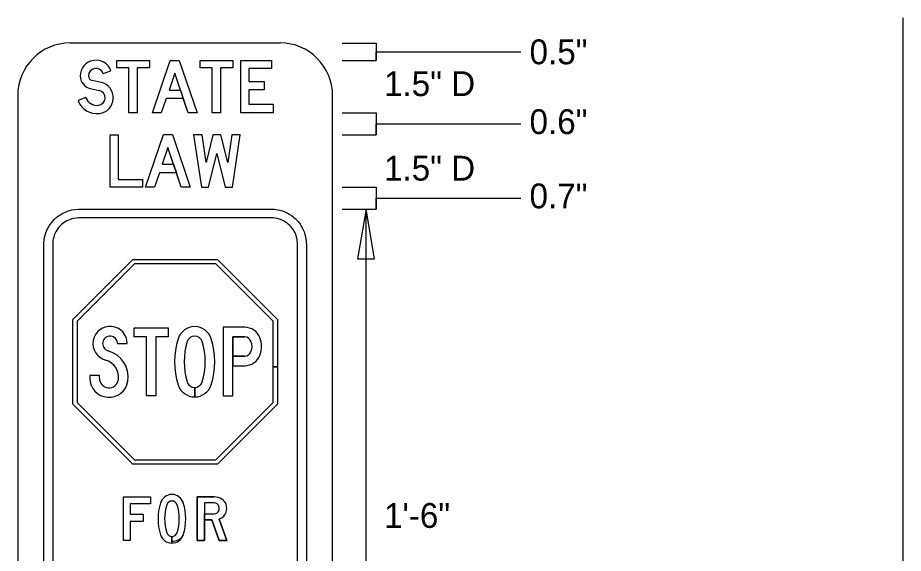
# Model space of a CAD drawing. Extents: x 0 to 770, y 0 to 495.
# Drawn here: x 260.2 to 385, y 419.5 to 495 of the extents above; entities that cross this region are included whole.
import ezdxf

# ---------------------------------------------------------------- set-up
doc = ezdxf.new("R2010")
doc.units = 0
for name, color, linetype in [('Default', 7, 'Continuous'), ('Dimension', 7, 'Continuous'), ('GSBWFill', 7, 'Continuous'), ('GSColorFill', 7, 'Continuous'), ('GSDims', 7, 'Continuous'), ('GSOutline', 7, 'Continuous'), ('SheetLines_dp', 7, 'Continuous'), ('TextStructures', 7, 'Continuous')]:
    doc.layers.add(name, color=color, linetype=linetype)

msp = doc.modelspace()

# ---------------------------------------------------------------- linework, layer by layer
at = {"layer": 'Default'}
for p, q in [((297.18, 491.43), (267.6, 491.43)), ((291.63, 488.97), (295.98, 488.97)), ((260.2, 484.04), (260.2, 365.71)), ((304.58, 365.71), (304.58, 484.04)), ((296.21, 481.59), (291.63, 481.59)), ((285.48, 421.32), (285.48, 427.46))]:
    msp.add_line(p, q, dxfattribs=at)
for points in [[(310.71, 491.42), (310.71, 488.96), (310.71, 490.19), (331.12, 490.19)], [(310.71, 481.58), (310.71, 478.49), (310.71, 480.04), (331.12, 480.04)], [(310.71, 471.11), (310.71, 468.02), (310.71, 469.56), (331.12, 469.56)], [(263.9, 384.2), (263.9, 463.08), (263.94, 463.74), (264.04, 464.23), (264.17, 464.68), (264.34, 465.13), (264.64, 465.68), (264.64, 465.68), (265.34, 466.57), (265.79, 466.97), (265.79, 466.97), (266.4, 467.37), (266.4, 467.37), (267.24, 467.75), (267.24, 467.75), (267.83, 467.91), (267.83, 467.91), (268.83, 468.01), (295.95, 468.01), (296.37, 468), (296.58, 467.97), (297.15, 467.87), (297.52, 467.76), (298.16, 467.49), (298.46, 467.32), (298.77, 467.12), (298.98, 466.98), (299.09, 466.89), (299.28, 466.72), (299.43, 466.57), (299.62, 466.37), (299.76, 466.21), (300, 465.89), (300.17, 465.63), (300.31, 465.38), (300.57, 464.81), (300.63, 464.63), (300.68, 464.46), (300.73, 464.29), (300.78, 464.05), (300.82, 463.84), (300.86, 463.5), (300.87, 463.33), (300.88, 463.08), (300.88, 417.5)], [(299.65, 417.5), (299.65, 463.08), (299.58, 463.76), (299.58, 463.76), (299.39, 464.44), (299.39, 464.44), (299.29, 464.66), (299.29, 464.66), (299.15, 464.93), (299.01, 465.16), (299.01, 465.16), (298.9, 465.31), (298.72, 465.53), (298.56, 465.7), (298.32, 465.92), (298.14, 466.07), (298.01, 466.15), (297.73, 466.33), (297.43, 466.47), (297.24, 466.55), (296.76, 466.69), (296.49, 466.74), (296.19, 466.77), (295.95, 466.78), (268.83, 466.78), (268.43, 466.76), (267.98, 466.68), (267.58, 466.56), (267.11, 466.36), (266.74, 466.13), (266.41, 465.88), (266.22, 465.7), (265.96, 465.42), (265.8, 465.2), (265.63, 464.93), (265.52, 464.72), (265.36, 464.35), (265.27, 464.09), (265.21, 463.82), (265.16, 463.56), (265.13, 463.08), (265.13, 384.2)]]:
    msp.add_lwpolyline(points, dxfattribs=at)
for points in [[(274.17, 488.97), (278.76, 488.97), (278.76, 487.94), (277.04, 487.94), (277.04, 481.59), (275.85, 481.59), (275.85, 487.94), (274.17, 487.94)], [(285.92, 488.97), (290.52, 488.97), (290.52, 487.94), (288.79, 487.94), (288.79, 481.59), (287.61, 481.59), (287.61, 487.94), (285.92, 487.94)], [(291.63, 488.97), (295.98, 488.97), (295.98, 487.82), (292.77, 487.82), (292.77, 486.01), (294.95, 486.01), (294.95, 484.83), (292.77, 484.83), (292.77, 482.8), (296.21, 482.8), (296.21, 481.59), (291.63, 481.59)], [(277.79, 472.19), (277.79, 471.12), (273.21, 471.12), (273.21, 478.5), (274.35, 478.5), (274.35, 472.19)], [(284.98, 478.5), (286.08, 471.12), (287.11, 471.12), (288.25, 475.86), (289.42, 471.12), (290.46, 471.12), (291.55, 478.5), (290.36, 478.5), (289.79, 474.61), (288.83, 478.5), (287.69, 478.5), (286.75, 474.61), (286.18, 478.5)], [(296.21, 445.78), (296.81, 445.78), (296.81, 440.53), (288.36, 432.08), (276.42, 432.08), (267.97, 440.53), (267.97, 452.48), (276.42, 460.93), (288.36, 460.93), (296.81, 452.48), (296.81, 445.78), (296.21, 445.78), (296.21, 452.23), (288.11, 460.33), (276.66, 460.33), (268.57, 452.23), (268.57, 440.78), (276.66, 432.68), (288.11, 432.68), (296.21, 440.78)], [(276.6, 451.31), (281.41, 451.31), (281.41, 450.04), (279.68, 450.04), (279.68, 441.7), (278.33, 441.7), (278.33, 450.04), (276.6, 450.04)], [(275.12, 427.46), (278.93, 427.46), (278.93, 426.5), (276.07, 426.5), (276.07, 425), (277.86, 425), (277.86, 424.01), (276.07, 424.01), (276.07, 421.32), (275.12, 421.32)]]:
    msp.add_lwpolyline(points, close=True, dxfattribs=at)
for centre, radius, start, end in [((267.6, 484.04), 7.4, 90, 180), ((297.18, 484.04), 7.4, 0, 90), ((282.02, 423.02), 1.81, 267.6237, 323.7302)]:
    msp.add_arc(centre, radius, start, end, dxfattribs=at)
at = {"layer": 'Dimension'}
msp.add_lwpolyline([(309.29, 468), (308.1, 460.99), (310.48, 460.99)], close=True, dxfattribs=at)
at = {"layer": 'GSBWFill'}
for p, q in [((272.23, 487.15), (273.33, 487.53)), ((271.94, 485.88), (270.68, 486.16)), ((270.42, 485.03), (271.68, 484.74)), ((269.8, 483.73), (268.71, 483.32)), ((274.28, 449.07), (275.63, 449.07)), ((271.72, 444.19), (271.72, 444.56)), ((285.14, 442.89), (285.14, 441.55)), ((285.14, 441.55), (285.14, 442.89)), ((287.88, 425.07), (287.88, 425.07)), ((281.93, 421.87), (281.93, 420.95)), ((281.93, 420.95), (281.93, 421.87))]:
    msp.add_line(p, q, dxfattribs=at)
for points in [[(279.2, 481.59), (281.71, 488.99), (282.97, 488.99), (285.48, 481.59), (284.23, 481.59), (282.34, 487.16), (281.54, 484.81), (283.14, 484.81), (283.54, 483.63), (281.14, 483.63), (280.44, 481.59)], [(278.23, 471.12), (280.74, 478.52), (282, 478.52), (284.51, 471.12), (283.26, 471.12), (281.37, 476.69), (280.57, 474.34), (282.17, 474.34), (282.57, 473.15), (280.17, 473.15), (279.48, 471.12)]]:
    msp.add_lwpolyline(points, close=True, dxfattribs=at)
for points in [[(292.21, 451.36), (289.16, 451.36), (289.16, 441.7), (290.51, 441.7), (290.51, 450.01), (292.21, 450.01)], [(292.21, 447.31), (290.51, 447.31), (290.51, 445.95), (292.21, 445.95)], [(271.72, 444.56), (270.37, 444.56), (270.37, 444.19)], [(287.88, 426.61), (286.52, 426.61), (286.52, 421.32), (285.48, 421.32), (285.48, 427.47), (287.88, 427.47)], [(288.61, 424.34), (289.66, 421.32), (288.57, 421.32), (287.57, 424.21), (286.52, 424.21), (286.52, 425.07), (287.88, 425.07)]]:
    msp.add_lwpolyline(points, dxfattribs=at)
for centre, radius, start, end in [((271.23, 486.8), 2.22, 19.1395, 180), ((270.83, 486.8), 1.82, 180, 257.1915), ((271.23, 486.8), 1.06, 19.1395, 180), ((270.83, 486.8), 0.656, 180, 257.1915), ((271.45, 483.71), 2.22, 276.7854, 77.1915), ((271.45, 483.71), 1.06, 276.7854, 77.1915), ((271.37, 484.32), 2.84, 200.6442, 276.7854), ((271.37, 484.32), 1.68, 200.6442, 276.7854), ((273.22, 449.07), 2.42, 0, 254.2259), ((285.14, 449.02), 2.44, 17.3283, 162.6717), ((292.21, 449.09), 2.27, 21.1002, 90), ((273.22, 449.07), 1.06, 0, 254.2259), ((293.2, 446.5), 10.88, 162.6717, 197.3283), ((293.2, 446.5), 9.54, 162.6717, 197.3283), ((285.14, 449.02), 1.1, 17.3283, 162.6717), ((277.09, 446.5), 9.54, 342.6717, 17.3283), ((277.09, 446.5), 10.88, 342.6717, 17.3283), ((292.21, 449.09), 0.918, 21.1002, 90), ((291.09, 448.66), 2.13, 338.8998, 21.1002), ((291.09, 448.66), 3.48, 338.8998, 21.1002), ((271.87, 444.28), 3.91, 352.1298, 74.2259), ((292.21, 448.22), 0.918, 270, 338.8998), ((292.21, 448.22), 2.27, 270, 338.8998), ((271.87, 444.28), 2.56, 352.5804, 74.2259), ((273.07, 444.19), 2.7, 180, 350.5313), ((273.07, 444.19), 1.35, 180, 349.7857), ((285.14, 443.99), 2.44, 197.3283, 270), ((285.14, 443.99), 1.1, 197.3283, 270), ((285.14, 443.99), 1.1, 270.0249, 342.6717), ((285.14, 443.99), 2.44, 270.0112, 342.6717), ((281.93, 426.11), 1.69, 17.3283, 162.6717), ((281.93, 426.11), 0.761, 17.3283, 162.6717), ((287.5, 424.37), 7.52, 162.6717, 197.3283), ((287.5, 424.37), 6.6, 162.6717, 197.3283), ((276.36, 424.37), 6.6, 342.6717, 17.3283), ((276.36, 424.37), 7.52, 342.6717, 17.3283), ((281.93, 422.63), 1.69, 197.3283, 270), ((281.93, 422.63), 0.761, 197.3283, 270), ((281.93, 422.63), 0.761, 270.0249, 342.6717), ((281.93, 422.63), 1.69, 270.0112, 342.6717)]:
    msp.add_arc(centre, radius, start, end, dxfattribs=at)
for centre, major_axis, start_param, end_param in [((287.88, 426.02), (1.75, 0), 0.242366, 1.570796), ((287.88, 426.02), (0.709, 0), 0.242366, 1.570796), ((286.97, 425.84), (1.64, 0), 6.040819, 6.525551), ((286.97, 425.84), (2.69, 0), 6.040819, 6.525551), ((287.88, 425.65), (0.709, 0), 4.712389, 6.040819), ((287.88, 425.65), (1.75, 0), 5.145616, 6.040819)]:
    msp.add_ellipse(centre, major_axis=major_axis, ratio=0.823178, start_param=start_param, end_param=end_param, dxfattribs=at)
at = {"layer": 'GSColorFill'}
for p, q in [((272.23, 487.15), (273.33, 487.53)), ((271.94, 485.88), (270.68, 486.16)), ((270.42, 485.03), (271.68, 484.74)), ((269.8, 483.73), (268.71, 483.32)), ((274.28, 449.07), (275.63, 449.07)), ((271.72, 444.19), (271.72, 444.56)), ((285.14, 442.89), (285.14, 441.55)), ((285.14, 441.55), (285.14, 442.89)), ((287.88, 425.07), (287.88, 425.07)), ((281.93, 421.87), (281.93, 420.95)), ((281.93, 420.95), (281.93, 421.87))]:
    msp.add_line(p, q, dxfattribs=at)
for points in [[(279.2, 481.59), (281.71, 488.99), (282.97, 488.99), (285.48, 481.59), (284.23, 481.59), (282.34, 487.16), (281.54, 484.81), (283.14, 484.81), (283.54, 483.63), (281.14, 483.63), (280.44, 481.59)], [(278.23, 471.12), (280.74, 478.52), (282, 478.52), (284.51, 471.12), (283.26, 471.12), (281.37, 476.69), (280.57, 474.34), (282.17, 474.34), (282.57, 473.15), (280.17, 473.15), (279.48, 471.12)]]:
    msp.add_lwpolyline(points, close=True, dxfattribs=at)
for points in [[(292.21, 451.36), (289.16, 451.36), (289.16, 441.7), (290.51, 441.7), (290.51, 450.01), (292.21, 450.01)], [(292.21, 447.31), (290.51, 447.31), (290.51, 445.95), (292.21, 445.95)], [(271.72, 444.56), (270.37, 444.56), (270.37, 444.19)], [(287.88, 426.61), (286.52, 426.61), (286.52, 421.32), (285.48, 421.32), (285.48, 427.47), (287.88, 427.47)], [(288.61, 424.34), (289.66, 421.32), (288.57, 421.32), (287.57, 424.21), (286.52, 424.21), (286.52, 425.07), (287.88, 425.07)]]:
    msp.add_lwpolyline(points, dxfattribs=at)
for centre, radius, start, end in [((271.23, 486.8), 2.22, 19.1395, 180), ((270.83, 486.8), 1.82, 180, 257.1915), ((271.23, 486.8), 1.06, 19.1395, 180), ((270.83, 486.8), 0.656, 180, 257.1915), ((271.45, 483.71), 2.22, 276.7854, 77.1915), ((271.45, 483.71), 1.06, 276.7854, 77.1915), ((271.37, 484.32), 2.84, 200.6442, 276.7854), ((271.37, 484.32), 1.68, 200.6442, 276.7854), ((273.22, 449.07), 2.42, 0, 254.2259), ((285.14, 449.02), 2.44, 17.3283, 162.6717), ((292.21, 449.09), 2.27, 21.1002, 90), ((273.22, 449.07), 1.06, 0, 254.2259), ((293.2, 446.5), 10.88, 162.6717, 197.3283), ((293.2, 446.5), 9.54, 162.6717, 197.3283), ((285.14, 449.02), 1.1, 17.3283, 162.6717), ((277.09, 446.5), 9.54, 342.6717, 17.3283), ((277.09, 446.5), 10.88, 342.6717, 17.3283), ((292.21, 449.09), 0.918, 21.1002, 90), ((291.09, 448.66), 2.13, 338.8998, 21.1002), ((291.09, 448.66), 3.48, 338.8998, 21.1002), ((271.87, 444.28), 3.91, 352.1298, 74.2259), ((292.21, 448.22), 0.918, 270, 338.8998), ((292.21, 448.22), 2.27, 270, 338.8998), ((271.87, 444.28), 2.56, 352.5804, 74.2259), ((273.07, 444.19), 2.7, 180, 350.5313), ((273.07, 444.19), 1.35, 180, 349.7857), ((285.14, 443.99), 2.44, 197.3283, 270), ((285.14, 443.99), 1.1, 197.3283, 270), ((285.14, 443.99), 1.1, 270.0249, 342.6717), ((285.14, 443.99), 2.44, 270.0112, 342.6717), ((281.93, 426.11), 1.69, 17.3283, 162.6717), ((281.93, 426.11), 0.761, 17.3283, 162.6717), ((287.5, 424.37), 7.52, 162.6717, 197.3283), ((287.5, 424.37), 6.6, 162.6717, 197.3283), ((276.36, 424.37), 6.6, 342.6717, 17.3283), ((276.36, 424.37), 7.52, 342.6717, 17.3283), ((281.93, 422.63), 1.69, 197.3283, 270), ((281.93, 422.63), 0.761, 197.3283, 270), ((281.93, 422.63), 0.761, 270.0249, 342.6717), ((281.93, 422.63), 1.69, 270.0112, 342.6717)]:
    msp.add_arc(centre, radius, start, end, dxfattribs=at)
for centre, major_axis, start_param, end_param in [((287.88, 426.02), (1.75, 0), 0.242366, 1.570796), ((287.88, 426.02), (0.709, 0), 0.242366, 1.570796), ((286.97, 425.84), (1.64, 0), 6.040819, 6.525551), ((286.97, 425.84), (2.69, 0), 6.040819, 6.525551), ((287.88, 425.65), (0.709, 0), 4.712389, 6.040819), ((287.88, 425.65), (1.75, 0), 5.145616, 6.040819)]:
    msp.add_ellipse(centre, major_axis=major_axis, ratio=0.823178, start_param=start_param, end_param=end_param, dxfattribs=at)
at = {"layer": 'GSDims'}
for p, q in [((305.91, 491.42), (310.71, 491.42)), ((305.91, 488.96), (310.71, 488.96)), ((305.91, 481.58), (310.71, 481.58)), ((305.91, 478.49), (310.71, 478.49)), ((305.91, 471.11), (310.71, 471.11)), ((305.91, 468), (310.71, 468)), ((309.29, 379.26), (309.29, 468))]:
    msp.add_line(p, q, dxfattribs=at)
at = {"layer": 'GSOutline'}
for p, q in [((272.23, 487.15), (273.33, 487.53)), ((271.94, 485.88), (270.68, 486.16)), ((270.42, 485.03), (271.68, 484.74)), ((269.8, 483.73), (268.71, 483.32)), ((292.21, 451.36), (289.16, 451.36)), ((274.28, 449.07), (275.63, 449.07)), ((271.72, 444.19), (271.72, 444.56)), ((287.88, 427.47), (285.48, 427.47)), ((287.88, 426.61), (287.88, 426.61))]:
    msp.add_line(p, q, dxfattribs=at)
for points in [[(281.14, 483.63), (280.44, 481.59), (279.2, 481.59), (281.71, 488.99), (282.97, 488.99), (285.48, 481.59), (284.23, 481.59), (283.54, 483.63)], [(281.54, 484.81), (283.14, 484.81), (282.34, 487.16)], [(280.17, 473.15), (279.48, 471.12), (278.23, 471.12), (280.74, 478.52), (282, 478.52), (284.51, 471.12), (283.26, 471.12), (282.57, 473.15)], [(280.57, 474.34), (282.17, 474.34), (281.37, 476.69)]]:
    msp.add_lwpolyline(points, close=True, dxfattribs=at)
for points in [[(289.16, 451.36), (289.16, 441.7), (290.51, 441.7), (290.51, 445.95), (292.21, 445.95)], [(292.21, 450.01), (290.51, 450.01), (290.51, 447.31), (292.21, 447.31)], [(271.72, 444.56), (270.37, 444.56), (270.37, 444.19)], [(285.48, 427.47), (285.48, 421.32), (286.52, 421.32), (286.52, 424.21), (287.57, 424.21), (288.57, 421.32), (289.66, 421.32), (288.61, 424.34)], [(287.88, 426.61), (286.52, 426.61), (286.52, 425.07), (287.88, 425.07)]]:
    msp.add_lwpolyline(points, dxfattribs=at)
for centre, radius, start, end in [((271.23, 486.8), 2.22, 19.1395, 180), ((270.83, 486.8), 1.82, 180, 257.1915), ((271.23, 486.8), 1.06, 19.1395, 180), ((270.83, 486.8), 0.656, 180, 257.1915), ((271.45, 483.71), 2.22, 276.7854, 77.1915), ((271.45, 483.71), 1.06, 276.7854, 77.1915), ((271.37, 484.32), 2.84, 200.6442, 276.7854), ((271.37, 484.32), 1.68, 200.6442, 276.7854), ((273.22, 449.07), 2.42, 0, 254.2259), ((285.14, 449.02), 2.44, 17.3283, 162.6717), ((292.21, 449.09), 2.27, 21.1002, 90), ((273.22, 449.07), 1.06, 0, 254.2259), ((293.2, 446.5), 10.88, 162.6717, 197.3283), ((293.2, 446.5), 9.54, 162.6717, 197.3283), ((285.14, 449.02), 1.1, 17.3283, 162.6717), ((277.09, 446.5), 9.54, 342.6717, 17.3283), ((277.09, 446.5), 10.88, 342.6717, 17.3283), ((292.21, 449.09), 0.918, 21.1002, 90), ((291.09, 448.66), 2.13, 338.8998, 21.1002), ((291.09, 448.66), 3.48, 338.8998, 21.1002), ((271.87, 444.28), 3.91, 352.1298, 74.2259), ((292.21, 448.22), 0.918, 270, 338.8998), ((292.21, 448.22), 2.27, 270, 338.8998), ((271.87, 444.28), 2.56, 352.5804, 74.2259), ((273.07, 444.19), 2.7, 180, 350.5313), ((273.07, 444.19), 1.35, 180, 349.7857), ((285.14, 443.99), 2.44, 197.3283, 342.6717), ((285.14, 443.99), 1.1, 197.3283, 342.6717), ((281.93, 426.11), 1.69, 17.3283, 162.6717), ((281.93, 426.11), 0.761, 17.3283, 162.6717), ((287.5, 424.37), 7.52, 162.6717, 197.3283), ((287.5, 424.37), 6.6, 162.6717, 197.3283), ((276.36, 424.37), 6.6, 342.6717, 17.3283), ((276.36, 424.37), 7.52, 342.6717, 17.3283), ((281.93, 422.63), 1.69, 197.3283, 342.6717), ((281.93, 422.63), 0.761, 197.3283, 342.6717)]:
    msp.add_arc(centre, radius, start, end, dxfattribs=at)
for centre, major_axis, start_param, end_param in [((287.88, 426.02), (1.75, 0), 0.242366, 1.570796), ((287.88, 426.02), (0.709, 0), 0.242366, 1.570796), ((286.97, 425.84), (1.64, 0), 6.040819, 6.525551), ((286.97, 425.84), (2.69, 0), 6.040819, 6.525551), ((287.88, 425.65), (0.709, 0), 4.712389, 6.040819), ((287.88, 425.65), (1.75, 0), 5.145616, 6.040819)]:
    msp.add_ellipse(centre, major_axis=major_axis, ratio=0.823178, start_param=start_param, end_param=end_param, dxfattribs=at)
at = {"layer": 'SheetLines_dp'}
msp.add_line((385, 0), (385, 495), dxfattribs=at)

# ---------------------------------------------------------------- texts
at = {"layer": 'TextStructures'}
for s, p in [('0.5"', (332.33, 488.44)), ('1.5" D', (311.82, 483.95)), ('0.6"', (332.33, 478.6)), ('1.5" D', (311.82, 472.04)), ('0.7"', (332.33, 468.13)), ('1\'-6"', (311.82, 423.09))]:
    msp.add_text(s, height=3.5, dxfattribs=at).set_placement(p)

doc.saveas('drawing.dxf')
